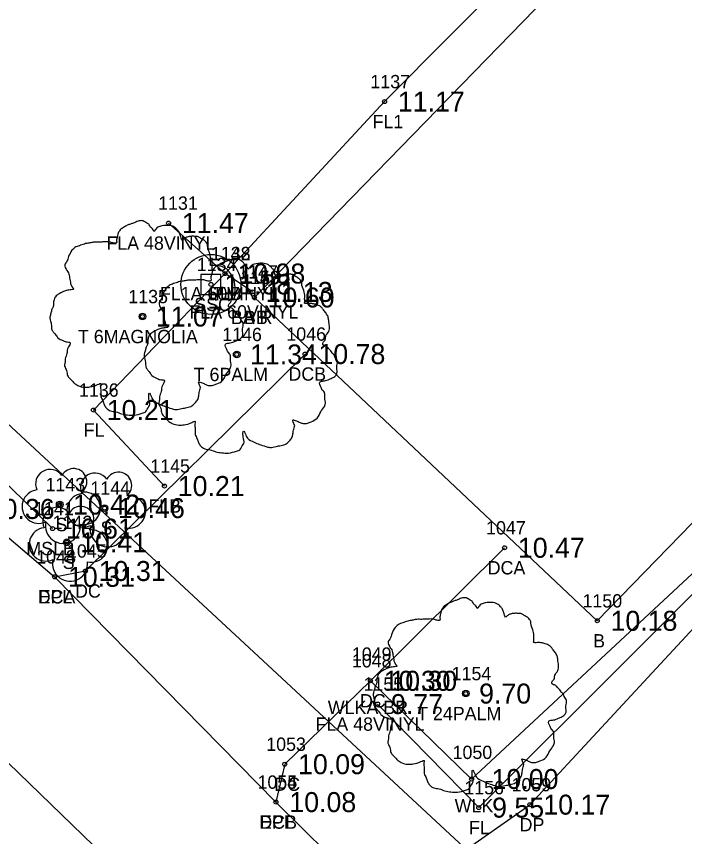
# Model space of a CAD drawing. Extents: x 2608598 to 2610682, y 641451 to 643526.
# Drawn here: x 2608826.7 to 2608876.9, y 643357.3 to 643418.9 of the extents above; entities that cross this region are included whole.
import ezdxf

# ---------------------------------------------------------------- set-up
doc = ezdxf.new("R2010")
doc.units = 0
for name, color, linetype in [('RD_EX_Bldg', 7, 'Continuous'), ('RD_EX_Bldg_txCode', 7, 'Continuous'), ('RD_EX_Conc', 7, 'Continuous'), ('RD_EX_Conc_txCode', 7, 'Continuous'), ('RD_EX_DR_Pipe', 7, 'Continuous'), ('RD_EX_Driveway', 7, 'Continuous'), ('RD_EX_Driveway_txCode', 7, 'Continuous'), ('RD_EX_Fence_Other', 7, 'Continuous'), ('RD_EX_Fence_Other_txCode', 7, 'Continuous'), ('RD_EX_Misc', 7, 'Continuous'), ('RD_EX_Misc_txCode', 7, 'Continuous'), ('RD_EX_Road', 7, 'Continuous'), ('RD_EX_Road_txCode', 7, 'Continuous'), ('RD_EX_TX_Bldg_ELEV', 7, 'Continuous'), ('RD_EX_TX_Conc_ELEV', 7, 'Continuous'), ('RD_EX_TX_Driveway_ELEV', 7, 'Continuous'), ('RD_EX_TX_Fence_Other_ELEV', 7, 'Continuous'), ('RD_EX_TX_Misc_ELEV', 7, 'Continuous'), ('RD_EX_TX_Road_ELEV', 7, 'Continuous'), ('RD_EX_TX_UT_ELEV', 7, 'Continuous'), ('RD_EX_TX_VEG_ELEV', 7, 'Continuous'), ('RD_EX_UT', 7, 'Continuous'), ('RD_EX_UT_txCode', 7, 'Continuous'), ('RD_EX_VEG', 7, 'Continuous'), ('RD_EX_VEG_txCode', 7, 'Continuous'), ('RD_HC_Cl', 7, 'Continuous'), ('RD_SMD_Locator', 7, 'Continuous')]:
    doc.layers.add(name, color=color, linetype=linetype)

msp = doc.modelspace()

# ---------------------------------------------------------------- linework, layer by layer
at = {"layer": 'RD_EX_Bldg'}
msp.add_lwpolyline([(2608844.568, 643397.768), (2608870.293, 643373.504), (2608904.162, 643408.325), (2608878.437, 643432.589), (2608844.568, 643397.768)], dxfattribs=at)
at = {"layer": 'RD_EX_Conc'}
for points in [[(2608829.584, 643376.805), (2608831.896, 643377.243), (2608848.379, 643393.523)], [(2608863.343, 643378.986), (2608853.271, 643369.006), (2608846.847, 643362.746), (2608846.192, 643359.903)]]:
    msp.add_lwpolyline(points, dxfattribs=at)
at = {"layer": 'RD_EX_DR_Pipe'}
msp.add_line((2608906.801, 643313.376), (2608812.867, 643400.541), dxfattribs=at)
at = {"layer": 'RD_EX_Driveway'}
msp.add_lwpolyline([(2608852.068, 643354.1), (2608857.773, 643354.471), (2608865.25, 643359.709), (2608886.742, 643382.904), (2608886.162, 643384.715), (2608908.715, 643407.594), (2608922.163, 643418.704)], dxfattribs=at)
at = {"layer": 'RD_EX_Fence_Other'}
msp.add_line((2608844.423, 643398.184), (2608842.371, 643399.562), dxfattribs=at)
for points in [[(2608842.371, 643399.562), (2608854.339, 643412.464), (2608879.415, 643437.696), (2608891.827, 643449.858)], [(2608838.128, 643403.347), (2608842.371, 643399.562), (2608832.496, 643389.321), (2608837.823, 643383.618)], [(2608853.82, 643367.257), (2608861.407, 643359.487), (2608884.459, 643382.494), (2608881.801, 643385.335)]]:
    msp.add_lwpolyline(points, dxfattribs=at)
at = {"layer": 'RD_EX_Misc'}
msp.add_line((2608818.754, 643390.795), (2608829.429, 643380.424), dxfattribs=at)
msp.add_lwpolyline([(2608853.271, 643369.006), (2608860.867, 643361.634), (2608883.195, 643382.409), (2608881.217, 643384.393)], dxfattribs=at)
at = {"layer": 'RD_EX_Road'}
msp.add_lwpolyline([(2608823.565, 643381.898), (2608829.584, 643376.805), (2608846.192, 643359.903), (2608852.068, 643354.1), (2608873.124, 643334.611), (2608877.912, 643330.135), (2608897.264, 643311.51), (2608898.769, 643309.298), (2608970.3, 643240.177), (2609042.495, 643170.94), (2609058.512, 643155.458)], dxfattribs=at)
at = {"layer": 'RD_EX_UT'}
for p, q in [((2608842.062, 643399.496), (2608840.562, 643399.496)), ((2608840.562, 643399.496), (2608840.562, 643397.996)), ((2608842.062, 643397.996), (2608842.062, 643399.496)), ((2608840.562, 643397.996), (2608842.062, 643397.996))]:
    msp.add_line(p, q, dxfattribs=at)
msp.add_circle((2608841.312, 643398.746), 2.25, dxfattribs=at)
at = {"layer": 'RD_EX_VEG'}
for centre, radius in [((2608836.174, 643396.336), 0.25), ((2608836.162, 643396.317), 0.0001), ((2608843.244, 643393.489), 0.25), ((2608843.231, 643393.47), 0.0001), ((2608829.961, 643382.229), 0.25), ((2608833.331, 643381.96), 0.25), ((2608830.496, 643379.393), 0.25), ((2608860.434, 643368.045), 0.25), ((2608860.422, 643368.026), 0.0001)]:
    msp.add_circle(centre, radius, dxfattribs=at)
for centre, radius, start, end in [((2608829.24, 643383.776), 1.084, 34.97629, 204.75602), ((2608831.006, 643383.931), 0.995, 308.76261, 152.04674), ((2608832.61, 643383.507), 1.084, 34.97629, 204.75602), ((2608834.376, 643383.662), 0.995, 308.76261, 152.04674), ((2608828.397, 643382.073), 1.257, 96.45179, 294.73401), ((2608831.801, 643381.95), 1.218, 256.56668, 98.10463), ((2608831.767, 643381.805), 1.257, 96.45179, 294.73401), ((2608835.17, 643381.681), 1.218, 256.56668, 98.10463), ((2608829.775, 643380.941), 1.084, 34.97629, 204.75602), ((2608831.541, 643381.095), 0.995, 308.76261, 152.04674), ((2608830.207, 643380.633), 1.318, 166.88266, 5.75893), ((2608833.576, 643380.364), 1.318, 166.88266, 5.75893), ((2608828.932, 643379.238), 1.257, 96.45179, 294.73401), ((2608832.335, 643379.114), 1.218, 256.56668, 98.10463), ((2608830.741, 643377.797), 1.318, 166.88266, 5.75893)]:
    msp.add_arc(centre, radius, start, end, dxfattribs=at)
for points in [[(2608836.306, 643403.503), (2608836.006, 643403.528), (2608835.681, 643403.428), (2608835.432, 643403.328), (2608835.207, 643403.253), (2608834.982, 643403.153), (2608834.682, 643402.978), (2608834.457, 643402.778), (2608834.332, 643402.528), (2608834.282, 643402.303), (2608834.232, 643402.029), (2608834.232, 643401.854), (2608834.107, 643401.829), (2608833.957, 643401.854), (2608833.707, 643401.929), (2608833.457, 643401.929), (2608833.207, 643401.929), (2608832.858, 643401.904), (2608832.508, 643401.904), (2608832.233, 643401.854), (2608831.908, 643401.804), (2608831.533, 643401.679), (2608831.183, 643401.554), (2608830.884, 643401.304), (2608830.634, 643400.829), (2608830.509, 643400.479), (2608830.359, 643400.229), (2608830.509, 643399.78), (2608830.684, 643399.43), (2608830.709, 643399.23), (2608830.784, 643398.805), (2608830.884, 643398.58), (2608831.008, 643398.38), (2608830.934, 643398.355), (2608830.559, 643398.305), (2608830.259, 643398.205), (2608829.834, 643397.98), (2608829.609, 643397.755), (2608829.509, 643397.43), (2608829.484, 643397.081), (2608829.384, 643396.881), (2608829.309, 643396.606), (2608829.284, 643396.531), (2608829.234, 643396.206), (2608829.334, 643395.756), (2608829.359, 643395.406), (2608829.484, 643395.181), (2608829.634, 643395.007), (2608829.809, 643394.757), (2608830.209, 643394.532), (2608830.534, 643394.432), (2608830.734, 643394.407), (2608830.559, 643393.907), (2608830.509, 643393.557), (2608830.384, 643393.157), (2608830.384, 643393.082), (2608830.334, 643392.608), (2608830.484, 643392.283), (2608830.559, 643391.908), (2608830.734, 643391.683), (2608831.008, 643391.383), (2608831.333, 643391.158), (2608831.833, 643391.033), (2608832.233, 643391.058), (2608832.808, 643391.233), (2608833.058, 643391.308), (2608833.033, 643391.133), (2608833.058, 643390.758), (2608833.058, 643390.334), (2608833.207, 643390.009), (2608833.307, 643389.734), (2608833.457, 643389.484), (2608833.782, 643389.259), (2608834.182, 643389.184), (2608834.607, 643389.034), (2608835.057, 643388.959), (2608835.556, 643388.934), (2608836.156, 643389.084), (2608836.431, 643389.209), (2608836.531, 643389.384), (2608836.731, 643389.759), (2608836.681, 643389.984), (2608836.706, 643390.584), (2608836.806, 643390.409), (2608836.981, 643390.059), (2608837.481, 643389.759), (2608837.88, 643389.584), (2608838.355, 643389.434), (2608838.655, 643389.359), (2608839.13, 643389.434), (2608839.505, 643389.509), (2608839.88, 643389.634), (2608840.179, 643389.909), (2608840.354, 643390.184), (2608840.404, 643390.459), (2608840.479, 643390.833), (2608840.529, 643391.008)], [(2608840.529, 643391.008), (2608840.454, 643391.183), (2608840.404, 643391.433), (2608840.479, 643391.408), (2608840.654, 643391.358), (2608840.929, 643391.233), (2608841.154, 643391.158), (2608841.479, 643391.183), (2608841.754, 643391.283), (2608842.204, 643391.558), (2608842.478, 643392.033), (2608842.753, 643392.433), (2608842.828, 643392.758), (2608842.778, 643392.982), (2608842.753, 643393.482), (2608842.553, 643393.732), (2608842.503, 643393.857), (2608842.403, 643394.257), (2608842.478, 643394.307), (2608842.753, 643394.357), (2608843.128, 643394.482), (2608843.403, 643394.607), (2608843.628, 643394.782), (2608843.703, 643395.007), (2608843.678, 643395.406), (2608843.728, 643395.806), (2608843.653, 643395.956), (2608843.553, 643396.106), (2608843.478, 643396.306), (2608843.328, 643396.456), (2608843.228, 643396.606), (2608843.128, 643396.706), (2608843.003, 643396.856), (2608842.828, 643396.981), (2608842.678, 643397.031), (2608842.628, 643397.181), (2608842.778, 643397.381), (2608842.828, 643397.48), (2608842.853, 643397.705), (2608843.078, 643398.055), (2608843.128, 643398.455), (2608843.078, 643398.88), (2608843.028, 643399.155), (2608842.878, 643399.43), (2608842.678, 643399.68), (2608842.553, 643399.854), (2608842.378, 643399.979), (2608842.054, 643400.104), (2608841.804, 643400.154), (2608841.454, 643400.154), (2608841.254, 643400.204), (2608841.279, 643400.254), (2608841.279, 643400.404), (2608841.279, 643400.679), (2608841.204, 643401.129), (2608841.054, 643401.629), (2608841.054, 643401.654), (2608840.954, 643401.904), (2608840.729, 643402.103), (2608840.554, 643402.203), (2608840.354, 643402.328), (2608840.104, 643402.353), (2608839.805, 643402.353), (2608839.53, 643402.303), (2608839.33, 643402.203), (2608839.155, 643402.078), (2608839.08, 643402.228), (2608838.98, 643402.528), (2608838.93, 643402.678), (2608838.78, 643402.853), (2608838.555, 643403.053), (2608838.105, 643403.178), (2608837.481, 643403.103), (2608837.181, 643402.903), (2608837.031, 643402.728), (2608836.981, 643402.853), (2608836.781, 643403.053), (2608836.681, 643403.228), (2608836.506, 643403.353), (2608836.356, 643403.453), (2608836.256, 643403.503)], [(2608843.376, 643400.656), (2608843.076, 643400.681), (2608842.751, 643400.581), (2608842.501, 643400.482), (2608842.276, 643400.407), (2608842.051, 643400.307), (2608841.752, 643400.132), (2608841.527, 643399.932), (2608841.402, 643399.682), (2608841.352, 643399.457), (2608841.302, 643399.182), (2608841.302, 643399.007), (2608841.177, 643398.982), (2608841.027, 643399.007), (2608840.777, 643399.082), (2608840.527, 643399.082), (2608840.277, 643399.082), (2608839.927, 643399.057), (2608839.577, 643399.057), (2608839.303, 643399.007), (2608838.978, 643398.957), (2608838.603, 643398.832), (2608838.253, 643398.707), (2608837.953, 643398.457), (2608837.703, 643397.983), (2608837.578, 643397.633), (2608837.428, 643397.383), (2608837.578, 643396.933), (2608837.753, 643396.583), (2608837.778, 643396.383), (2608837.853, 643395.959), (2608837.953, 643395.734), (2608838.078, 643395.534), (2608838.003, 643395.509), (2608837.628, 643395.459), (2608837.328, 643395.359), (2608836.904, 643395.134), (2608836.679, 643394.909), (2608836.579, 643394.584), (2608836.554, 643394.234), (2608836.454, 643394.034), (2608836.379, 643393.759), (2608836.354, 643393.684), (2608836.304, 643393.36), (2608836.404, 643392.91), (2608836.429, 643392.56), (2608836.554, 643392.335), (2608836.704, 643392.16), (2608836.879, 643391.91), (2608837.278, 643391.685), (2608837.603, 643391.585), (2608837.803, 643391.56), (2608837.628, 643391.061), (2608837.578, 643390.711), (2608837.453, 643390.311), (2608837.453, 643390.236), (2608837.403, 643389.761), (2608837.553, 643389.436), (2608837.628, 643389.062), (2608837.803, 643388.837), (2608838.078, 643388.537), (2608838.403, 643388.312), (2608838.903, 643388.187), (2608839.303, 643388.212), (2608839.877, 643388.387), (2608840.127, 643388.462), (2608840.102, 643388.287), (2608840.127, 643387.912), (2608840.127, 643387.487), (2608840.277, 643387.162), (2608840.377, 643386.887), (2608840.527, 643386.638), (2608840.852, 643386.413), (2608841.252, 643386.338), (2608841.677, 643386.188), (2608842.126, 643386.113), (2608842.626, 643386.088), (2608843.226, 643386.238), (2608843.501, 643386.363), (2608843.601, 643386.538), (2608843.801, 643386.912), (2608843.751, 643387.137), (2608843.776, 643387.737), (2608843.876, 643387.562), (2608844.051, 643387.212), (2608844.55, 643386.912), (2608844.95, 643386.738), (2608845.425, 643386.588), (2608845.725, 643386.513), (2608846.2, 643386.588), (2608846.574, 643386.663), (2608846.949, 643386.788), (2608847.249, 643387.062), (2608847.424, 643387.337), (2608847.474, 643387.612), (2608847.549, 643387.987), (2608847.599, 643388.162)], [(2608847.599, 643388.162), (2608847.524, 643388.337), (2608847.474, 643388.587), (2608847.549, 643388.562), (2608847.724, 643388.512), (2608847.999, 643388.387), (2608848.224, 643388.312), (2608848.549, 643388.337), (2608848.823, 643388.437), (2608849.273, 643388.712), (2608849.548, 643389.186), (2608849.823, 643389.586), (2608849.898, 643389.911), (2608849.848, 643390.136), (2608849.823, 643390.636), (2608849.623, 643390.886), (2608849.573, 643391.011), (2608849.473, 643391.41), (2608849.548, 643391.46), (2608849.823, 643391.51), (2608850.198, 643391.635), (2608850.473, 643391.76), (2608850.698, 643391.935), (2608850.773, 643392.16), (2608850.748, 643392.56), (2608850.798, 643392.96), (2608850.723, 643393.11), (2608850.623, 643393.26), (2608850.548, 643393.46), (2608850.398, 643393.609), (2608850.298, 643393.759), (2608850.198, 643393.859), (2608850.073, 643394.009), (2608849.898, 643394.134), (2608849.748, 643394.184), (2608849.698, 643394.334), (2608849.848, 643394.534), (2608849.898, 643394.634), (2608849.923, 643394.859), (2608850.148, 643395.209), (2608850.198, 643395.609), (2608850.148, 643396.033), (2608850.098, 643396.308), (2608849.948, 643396.583), (2608849.748, 643396.833), (2608849.623, 643397.008), (2608849.448, 643397.133), (2608849.123, 643397.258), (2608848.873, 643397.308), (2608848.524, 643397.308), (2608848.324, 643397.358), (2608848.349, 643397.408), (2608848.349, 643397.558), (2608848.349, 643397.833), (2608848.274, 643398.282), (2608848.124, 643398.782), (2608848.124, 643398.807), (2608848.024, 643399.057), (2608847.799, 643399.257), (2608847.624, 643399.357), (2608847.424, 643399.482), (2608847.174, 643399.507), (2608846.874, 643399.507), (2608846.599, 643399.457), (2608846.399, 643399.357), (2608846.225, 643399.232), (2608846.15, 643399.382), (2608846.05, 643399.682), (2608846, 643399.832), (2608845.85, 643400.007), (2608845.625, 643400.207), (2608845.175, 643400.332), (2608844.55, 643400.257), (2608844.25, 643400.057), (2608844.1, 643399.882), (2608844.051, 643400.007), (2608843.851, 643400.207), (2608843.751, 643400.382), (2608843.576, 643400.507), (2608843.426, 643400.606), (2608843.326, 643400.656)], [(2608860.566, 643375.212), (2608860.266, 643375.237), (2608859.942, 643375.137), (2608859.692, 643375.037), (2608859.467, 643374.962), (2608859.242, 643374.862), (2608858.942, 643374.688), (2608858.717, 643374.488), (2608858.592, 643374.238), (2608858.542, 643374.013), (2608858.492, 643373.738), (2608858.492, 643373.563), (2608858.367, 643373.538), (2608858.217, 643373.563), (2608857.967, 643373.638), (2608857.717, 643373.638), (2608857.468, 643373.638), (2608857.118, 643373.613), (2608856.768, 643373.613), (2608856.493, 643373.563), (2608856.168, 643373.513), (2608855.793, 643373.388), (2608855.443, 643373.263), (2608855.144, 643373.013), (2608854.894, 643372.538), (2608854.769, 643372.189), (2608854.619, 643371.939), (2608854.769, 643371.489), (2608854.944, 643371.139), (2608854.969, 643370.939), (2608855.044, 643370.514), (2608855.144, 643370.289), (2608855.269, 643370.089), (2608855.194, 643370.065), (2608854.819, 643370.015), (2608854.519, 643369.915), (2608854.094, 643369.69), (2608853.869, 643369.465), (2608853.769, 643369.14), (2608853.744, 643368.79), (2608853.644, 643368.59), (2608853.569, 643368.315), (2608853.544, 643368.24), (2608853.494, 643367.915), (2608853.594, 643367.466), (2608853.619, 643367.116), (2608853.744, 643366.891), (2608853.894, 643366.716), (2608854.069, 643366.466), (2608854.469, 643366.241), (2608854.794, 643366.141), (2608854.994, 643366.116), (2608854.819, 643365.616), (2608854.769, 643365.267), (2608854.644, 643364.867), (2608854.644, 643364.792), (2608854.594, 643364.317), (2608854.744, 643363.992), (2608854.819, 643363.617), (2608854.994, 643363.392), (2608855.269, 643363.093), (2608855.593, 643362.868), (2608856.093, 643362.743), (2608856.493, 643362.768), (2608857.068, 643362.943), (2608857.318, 643363.018), (2608857.293, 643362.843), (2608857.318, 643362.468), (2608857.318, 643362.043), (2608857.468, 643361.718), (2608857.568, 643361.443), (2608857.717, 643361.193), (2608858.042, 643360.969), (2608858.442, 643360.894), (2608858.867, 643360.744), (2608859.317, 643360.669), (2608859.817, 643360.644), (2608860.416, 643360.794), (2608860.691, 643360.919), (2608860.791, 643361.093), (2608860.991, 643361.468), (2608860.941, 643361.693), (2608860.966, 643362.293), (2608861.066, 643362.118), (2608861.241, 643361.768), (2608861.741, 643361.468), (2608862.141, 643361.293), (2608862.615, 643361.143), (2608862.915, 643361.068), (2608863.39, 643361.143), (2608863.765, 643361.218), (2608864.14, 643361.343), (2608864.44, 643361.618), (2608864.614, 643361.893), (2608864.664, 643362.168), (2608864.739, 643362.543), (2608864.789, 643362.718)], [(2608864.789, 643362.718), (2608864.714, 643362.893), (2608864.664, 643363.143), (2608864.739, 643363.118), (2608864.914, 643363.068), (2608865.189, 643362.943), (2608865.414, 643362.868), (2608865.739, 643362.893), (2608866.014, 643362.993), (2608866.464, 643363.268), (2608866.739, 643363.742), (2608867.013, 643364.142), (2608867.088, 643364.467), (2608867.038, 643364.692), (2608867.013, 643365.192), (2608866.813, 643365.442), (2608866.763, 643365.566), (2608866.664, 643365.966), (2608866.739, 643366.016), (2608867.013, 643366.066), (2608867.388, 643366.191), (2608867.663, 643366.316), (2608867.888, 643366.491), (2608867.963, 643366.716), (2608867.938, 643367.116), (2608867.988, 643367.516), (2608867.913, 643367.666), (2608867.813, 643367.815), (2608867.738, 643368.015), (2608867.588, 643368.165), (2608867.488, 643368.315), (2608867.388, 643368.415), (2608867.263, 643368.565), (2608867.088, 643368.69), (2608866.938, 643368.74), (2608866.888, 643368.89), (2608867.038, 643369.09), (2608867.088, 643369.19), (2608867.113, 643369.415), (2608867.338, 643369.765), (2608867.388, 643370.164), (2608867.338, 643370.589), (2608867.288, 643370.864), (2608867.138, 643371.139), (2608866.938, 643371.389), (2608866.813, 643371.564), (2608866.639, 643371.689), (2608866.314, 643371.814), (2608866.064, 643371.864), (2608865.714, 643371.864), (2608865.514, 643371.914), (2608865.539, 643371.964), (2608865.539, 643372.114), (2608865.539, 643372.389), (2608865.464, 643372.838), (2608865.314, 643373.338), (2608865.314, 643373.363), (2608865.214, 643373.613), (2608864.989, 643373.813), (2608864.814, 643373.913), (2608864.614, 643374.038), (2608864.365, 643374.063), (2608864.065, 643374.063), (2608863.79, 643374.013), (2608863.59, 643373.913), (2608863.415, 643373.788), (2608863.34, 643373.938), (2608863.24, 643374.238), (2608863.19, 643374.388), (2608863.04, 643374.563), (2608862.815, 643374.762), (2608862.365, 643374.887), (2608861.741, 643374.812), (2608861.441, 643374.613), (2608861.291, 643374.438), (2608861.241, 643374.563), (2608861.041, 643374.762), (2608860.941, 643374.937), (2608860.766, 643375.062), (2608860.616, 643375.162), (2608860.516, 643375.212)]]:
    msp.add_spline(points, degree=3, dxfattribs=at)
at = {"layer": 'RD_HC_Cl'}
msp.add_line((2608814.812, 643373.733), (2610092.394, 642140.787), dxfattribs=at)
at = {"layer": 'RD_SMD_Locator'}
for centre in [(2608854.339, 643412.464), (2608838.128, 643403.347), (2608842.371, 643399.562), (2608842.371, 643399.562), (2608842.371, 643399.562), (2608841.312, 643398.746), (2608844.423, 643398.184), (2608844.568, 643397.768), (2608844.568, 643397.768), (2608836.174, 643396.336), (2608843.244, 643393.489), (2608848.379, 643393.523), (2608832.496, 643389.321), (2608837.823, 643383.618), (2608829.961, 643382.229), (2608833.331, 643381.96), (2608829.429, 643380.424), (2608830.496, 643379.393), (2608863.343, 643378.986), (2608831.896, 643377.243), (2608829.584, 643376.805), (2608829.584, 643376.805), (2608870.293, 643373.504), (2608853.271, 643369.006), (2608853.271, 643369.006), (2608860.434, 643368.045), (2608853.82, 643367.257), (2608846.847, 643362.746), (2608860.867, 643361.634), (2608846.192, 643359.903), (2608846.192, 643359.903), (2608865.25, 643359.709), (2608861.407, 643359.487)]:
    msp.add_circle(centre, 0.15, dxfattribs=at)

# ---------------------------------------------------------------- texts
at = {"layer": 'RD_EX_Bldg_txCode'}
for s, p in [('1149', (2608843.505, 643398.768)), ('1153', (2608843.505, 643398.768)), ('BA R', (2608842.812, 643395.768)), ('BB', (2608843.788, 643395.768)), ('1150', (2608869.191, 643374.504)), ('B', (2608869.986, 643371.504))]:
    msp.add_text(s, height=1, dxfattribs=at).set_placement(p)
at = {"layer": 'RD_EX_Conc_txCode'}
for s, p in [('1046', (2608846.97, 643394.523)), ('DCB', (2608847.128, 643391.523)), ('1047', (2608861.957, 643379.986)), ('1044', (2608828.198, 643377.805)), ('1045', (2608830.51, 643378.243)), ('DCA', (2608862.075, 643376.986)), ('DCA', (2608828.316, 643374.805)), ('DC', (2608831.116, 643375.243)), ('1048', (2608851.886, 643370.006)), ('DC', (2608852.492, 643367.006)), ('1053', (2608845.461, 643363.746)), ('1054', (2608844.806, 643360.903)), ('DC', (2608846.067, 643360.746)), ('DCB', (2608844.94, 643357.903))]:
    msp.add_text(s, height=1, dxfattribs=at).set_placement(p)
at = {"layer": 'RD_EX_Driveway_txCode'}
for s, p in [('1059', (2608863.864, 643360.709)), ('DP', (2608864.471, 643357.709))]:
    msp.add_text(s, height=1, dxfattribs=at).set_placement(p)
at = {"layer": 'RD_EX_Fence_Other_txCode'}
for s, p in [('1137', (2608853.276, 643413.464)), ('FL1', (2608853.441, 643410.464)), ('1131', (2608837.348, 643404.347)), ('FLA 48VINYL', (2608833.466, 643401.347)), ('1132', (2608841.308, 643400.562)), ('1133', (2608841.308, 643400.562)), ('1148', (2608841.308, 643400.562)), ('1147', (2608843.36, 643399.184)), ('FL1A 60VINYL', (2608837.481, 643397.562)), ('FLB', (2608841.166, 643397.562)), ('FL', (2608841.639, 643397.562)), ('FLA 60VINYL', (2608839.699, 643396.184)), ('1136', (2608831.409, 643390.321)), ('FL', (2608831.764, 643387.321)), ('1145', (2608836.76, 643384.618)), ('FLB', (2608836.619, 643381.618)), ('1155', (2608852.757, 643368.257)), ('FLA 48VINYL', (2608849.159, 643365.257)), ('1156', (2608860.32, 643360.487)), ('FL', (2608860.675, 643357.487))]:
    msp.add_text(s, height=1, dxfattribs=at).set_placement(p)
at = {"layer": 'RD_EX_Misc_txCode'}
for s, p in [('1141', (2608828.042, 643381.424)), ('MSLB', (2608827.459, 643378.424)), ('1049', (2608851.886, 643370.506)), ('WLKA BR', (2608850.082, 643366.506)), ('1050', (2608859.442, 643363.134)), ('WLK', (2608859.599, 643359.134))]:
    msp.add_text(s, height=1, dxfattribs=at).set_placement(p)
at = {"layer": 'RD_EX_Road_txCode'}
for s, p in [('1043', (2608828.198, 643377.805)), ('EPL', (2608828.379, 643374.805)), ('1055', (2608844.806, 643360.903)), ('EPL', (2608844.987, 643357.903))]:
    msp.add_text(s, height=1, dxfattribs=at).set_placement(p)
at = {"layer": 'RD_EX_TX_Bldg_ELEV'}
for s, p in [('10.60', (2608845.568, 643397.018)), ('10.60', (2608845.568, 643397.018)), ('10.18', (2608871.293, 643372.754))]:
    msp.add_text(s, height=1.5, dxfattribs=at).set_placement(p)
at = {"layer": 'RD_EX_TX_Conc_ELEV'}
for s, p in [('10.78', (2608849.379, 643392.773)), ('10.47', (2608864.343, 643378.236)), ('10.31', (2608832.896, 643376.493)), ('10.31', (2608830.584, 643376.055)), ('10.30', (2608854.271, 643368.256)), ('10.09', (2608847.847, 643361.996)), ('10.08', (2608847.192, 643359.153))]:
    msp.add_text(s, height=1.5, dxfattribs=at).set_placement(p)
at = {"layer": 'RD_EX_TX_Driveway_ELEV'}
msp.add_text('10.17', height=1.5, dxfattribs=at).set_placement((2608866.25, 643358.959))
at = {"layer": 'RD_EX_TX_Fence_Other_ELEV'}
for s, p in [('11.17', (2608855.339, 643411.714)), ('11.47', (2608839.128, 643402.597)), ('10.98', (2608843.371, 643398.812)), ('10.98', (2608843.371, 643398.812)), ('10.98', (2608843.371, 643398.812)), ('11.13', (2608845.423, 643397.434)), ('10.21', (2608833.496, 643388.571)), ('10.21', (2608838.823, 643382.868)), ('9.77', (2608854.82, 643366.507)), ('9.55', (2608862.407, 643358.737))]:
    msp.add_text(s, height=1.5, dxfattribs=at).set_placement(p)
at = {"layer": 'RD_EX_TX_Misc_ELEV'}
for s, p in [('10.61', (2608830.429, 643379.674)), ('10.30', (2608854.771, 643368.256)), ('10.00', (2608862.367, 643360.884))]:
    msp.add_text(s, height=1.5, dxfattribs=at).set_placement(p)
at = {"layer": 'RD_EX_TX_Road_ELEV'}
for s, p in [('10.36', (2608824.565, 643381.148)), ('10.31', (2608830.584, 643376.055)), ('10.08', (2608847.192, 643359.153))]:
    msp.add_text(s, height=1.5, dxfattribs=at).set_placement(p)
at = {"layer": 'RD_EX_TX_UT_ELEV'}
msp.add_text('11.08', height=1.5, dxfattribs=at).set_placement((2608842.312, 643397.996))
at = {"layer": 'RD_EX_TX_VEG_ELEV'}
for s, p in [('11.07', (2608837.174, 643395.586)), ('11.34', (2608844.244, 643392.739)), ('10.42', (2608830.961, 643381.479)), ('10.46', (2608834.331, 643381.21)), ('10.41', (2608831.496, 643378.643)), ('9.70', (2608861.434, 643367.295))]:
    msp.add_text(s, height=1.5, dxfattribs=at).set_placement(p)
at = {"layer": 'RD_EX_UT_txCode'}
for s, p in [('1134', (2608840.249, 643399.746)), ('SSC', (2608840.06, 643396.746))]:
    msp.add_text(s, height=1, dxfattribs=at).set_placement(p)
at = {"layer": 'RD_EX_VEG_txCode'}
for s, p in [('1135', (2608835.111, 643397.336)), ('1146', (2608842.157, 643394.489)), ('T 6MAGNOLIA', (2608831.332, 643394.336)), ('T 6PALM', (2608840.016, 643391.489)), ('1143', (2608828.898, 643383.229)), ('1144', (2608832.268, 643382.96)), ('1142', (2608829.433, 643380.393)), ('S', (2608829.654, 643380.229)), ('S', (2608833.024, 643379.96)), ('S', (2608830.189, 643377.393)), ('1154', (2608859.371, 643369.045)), ('T 24PALM', (2608856.781, 643366.045))]:
    msp.add_text(s, height=1, dxfattribs=at).set_placement(p)

doc.saveas('drawing.dxf')
